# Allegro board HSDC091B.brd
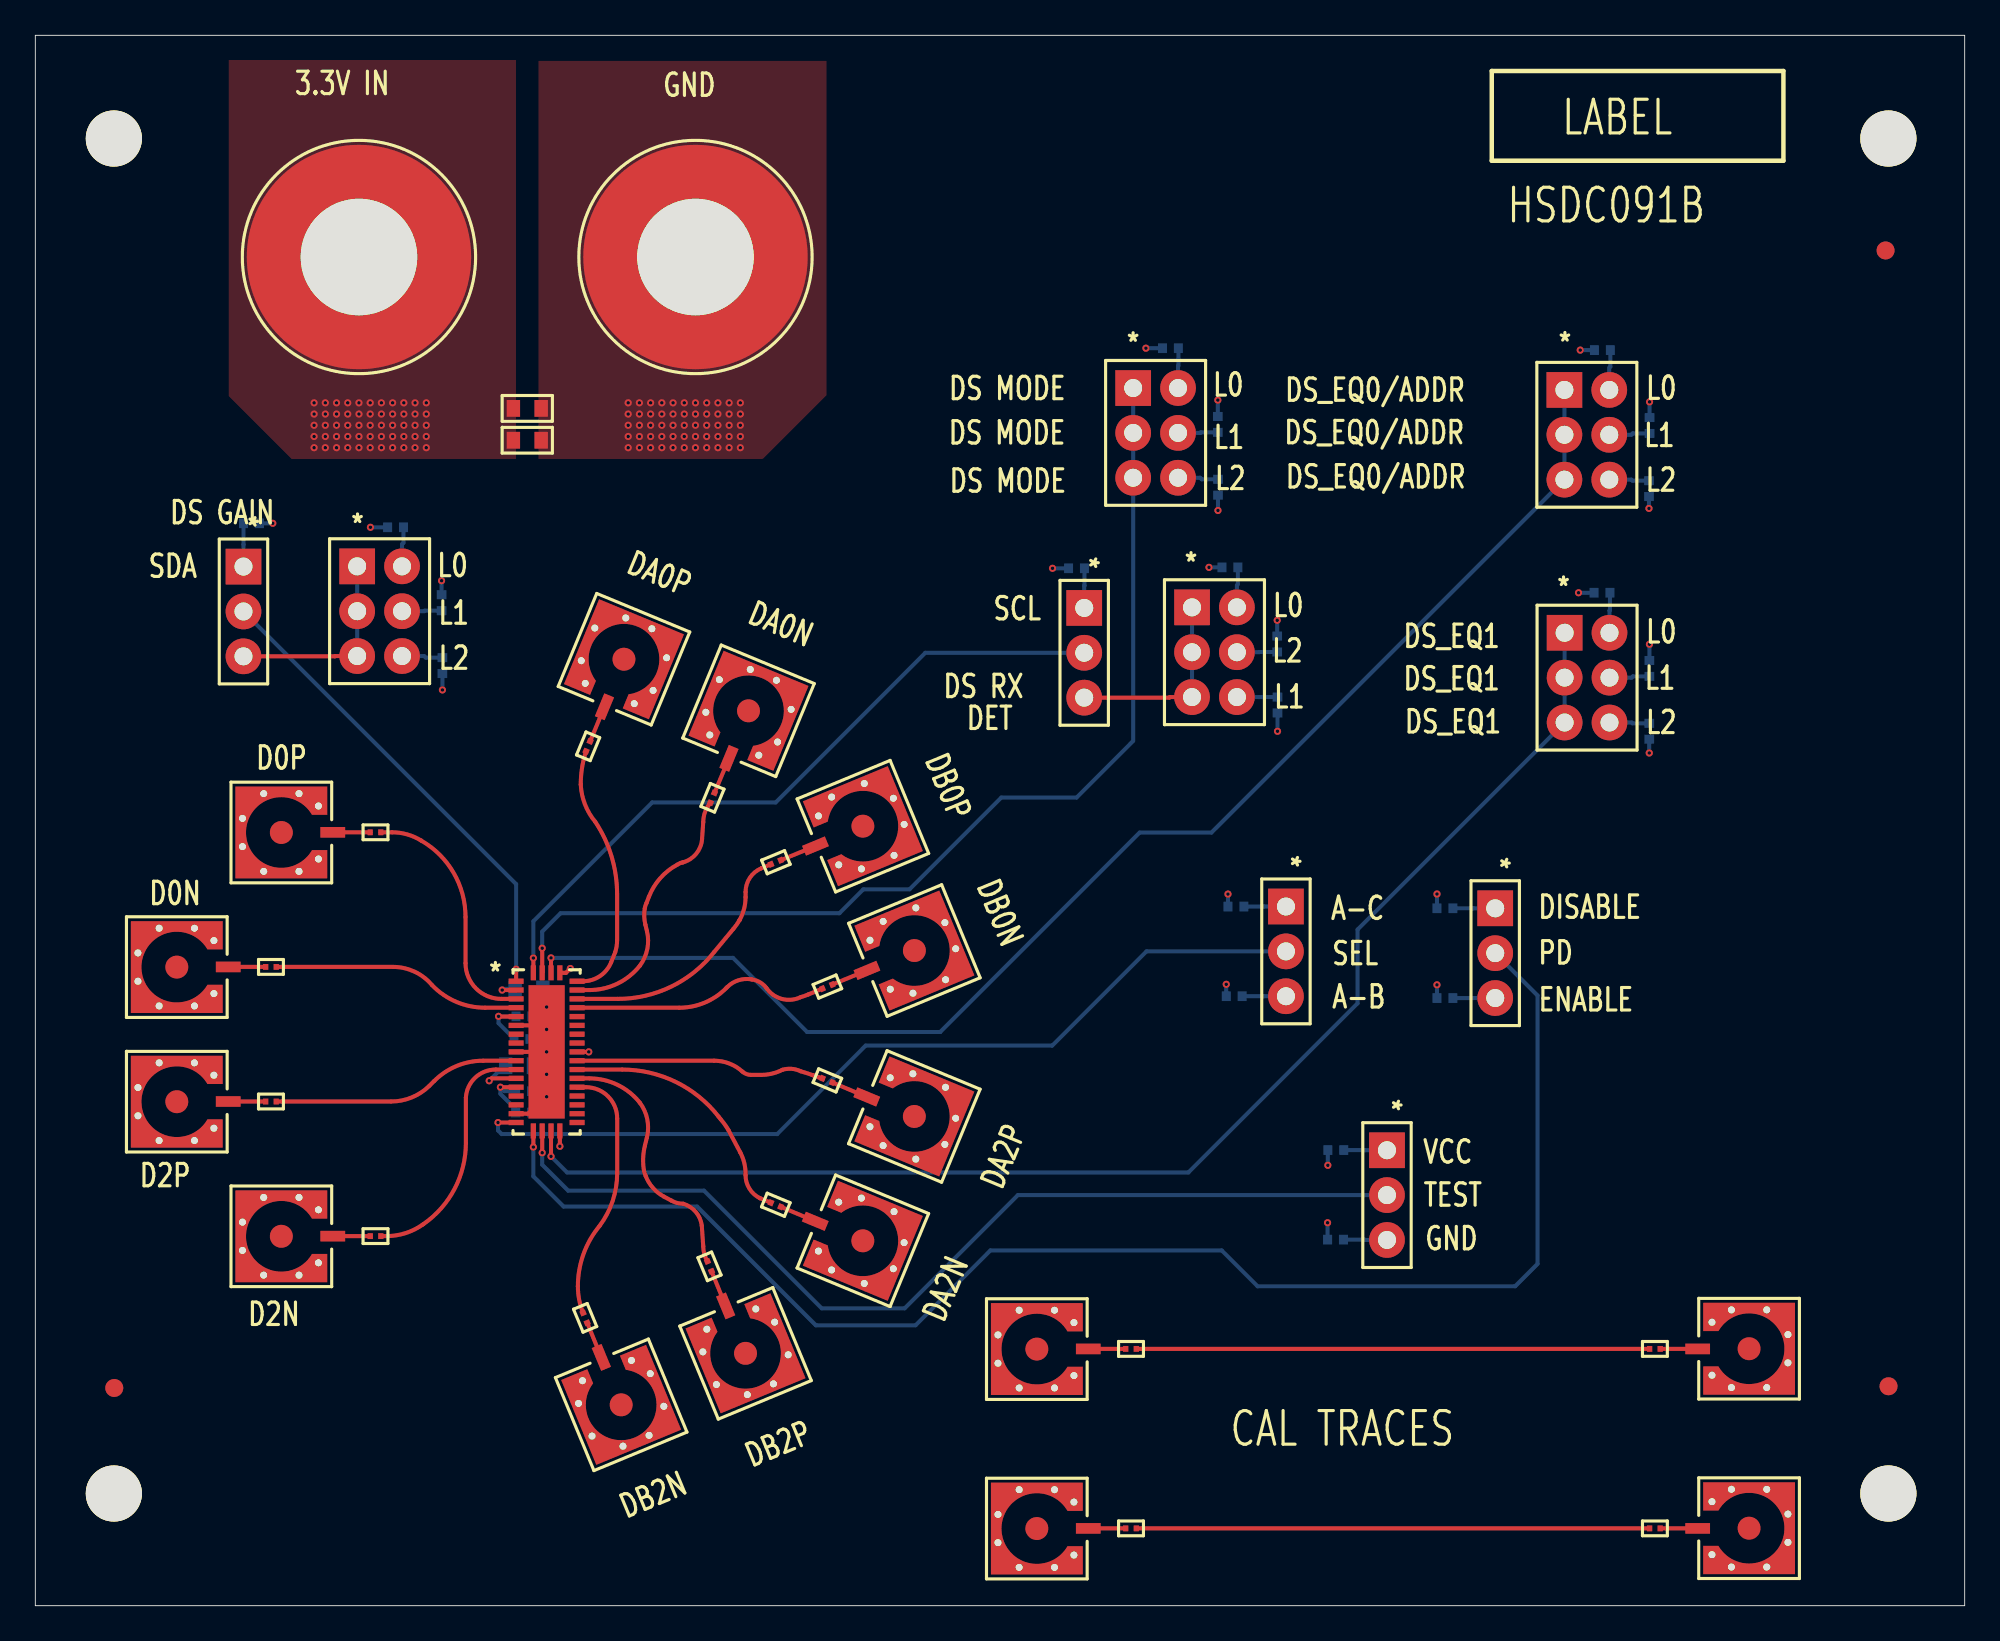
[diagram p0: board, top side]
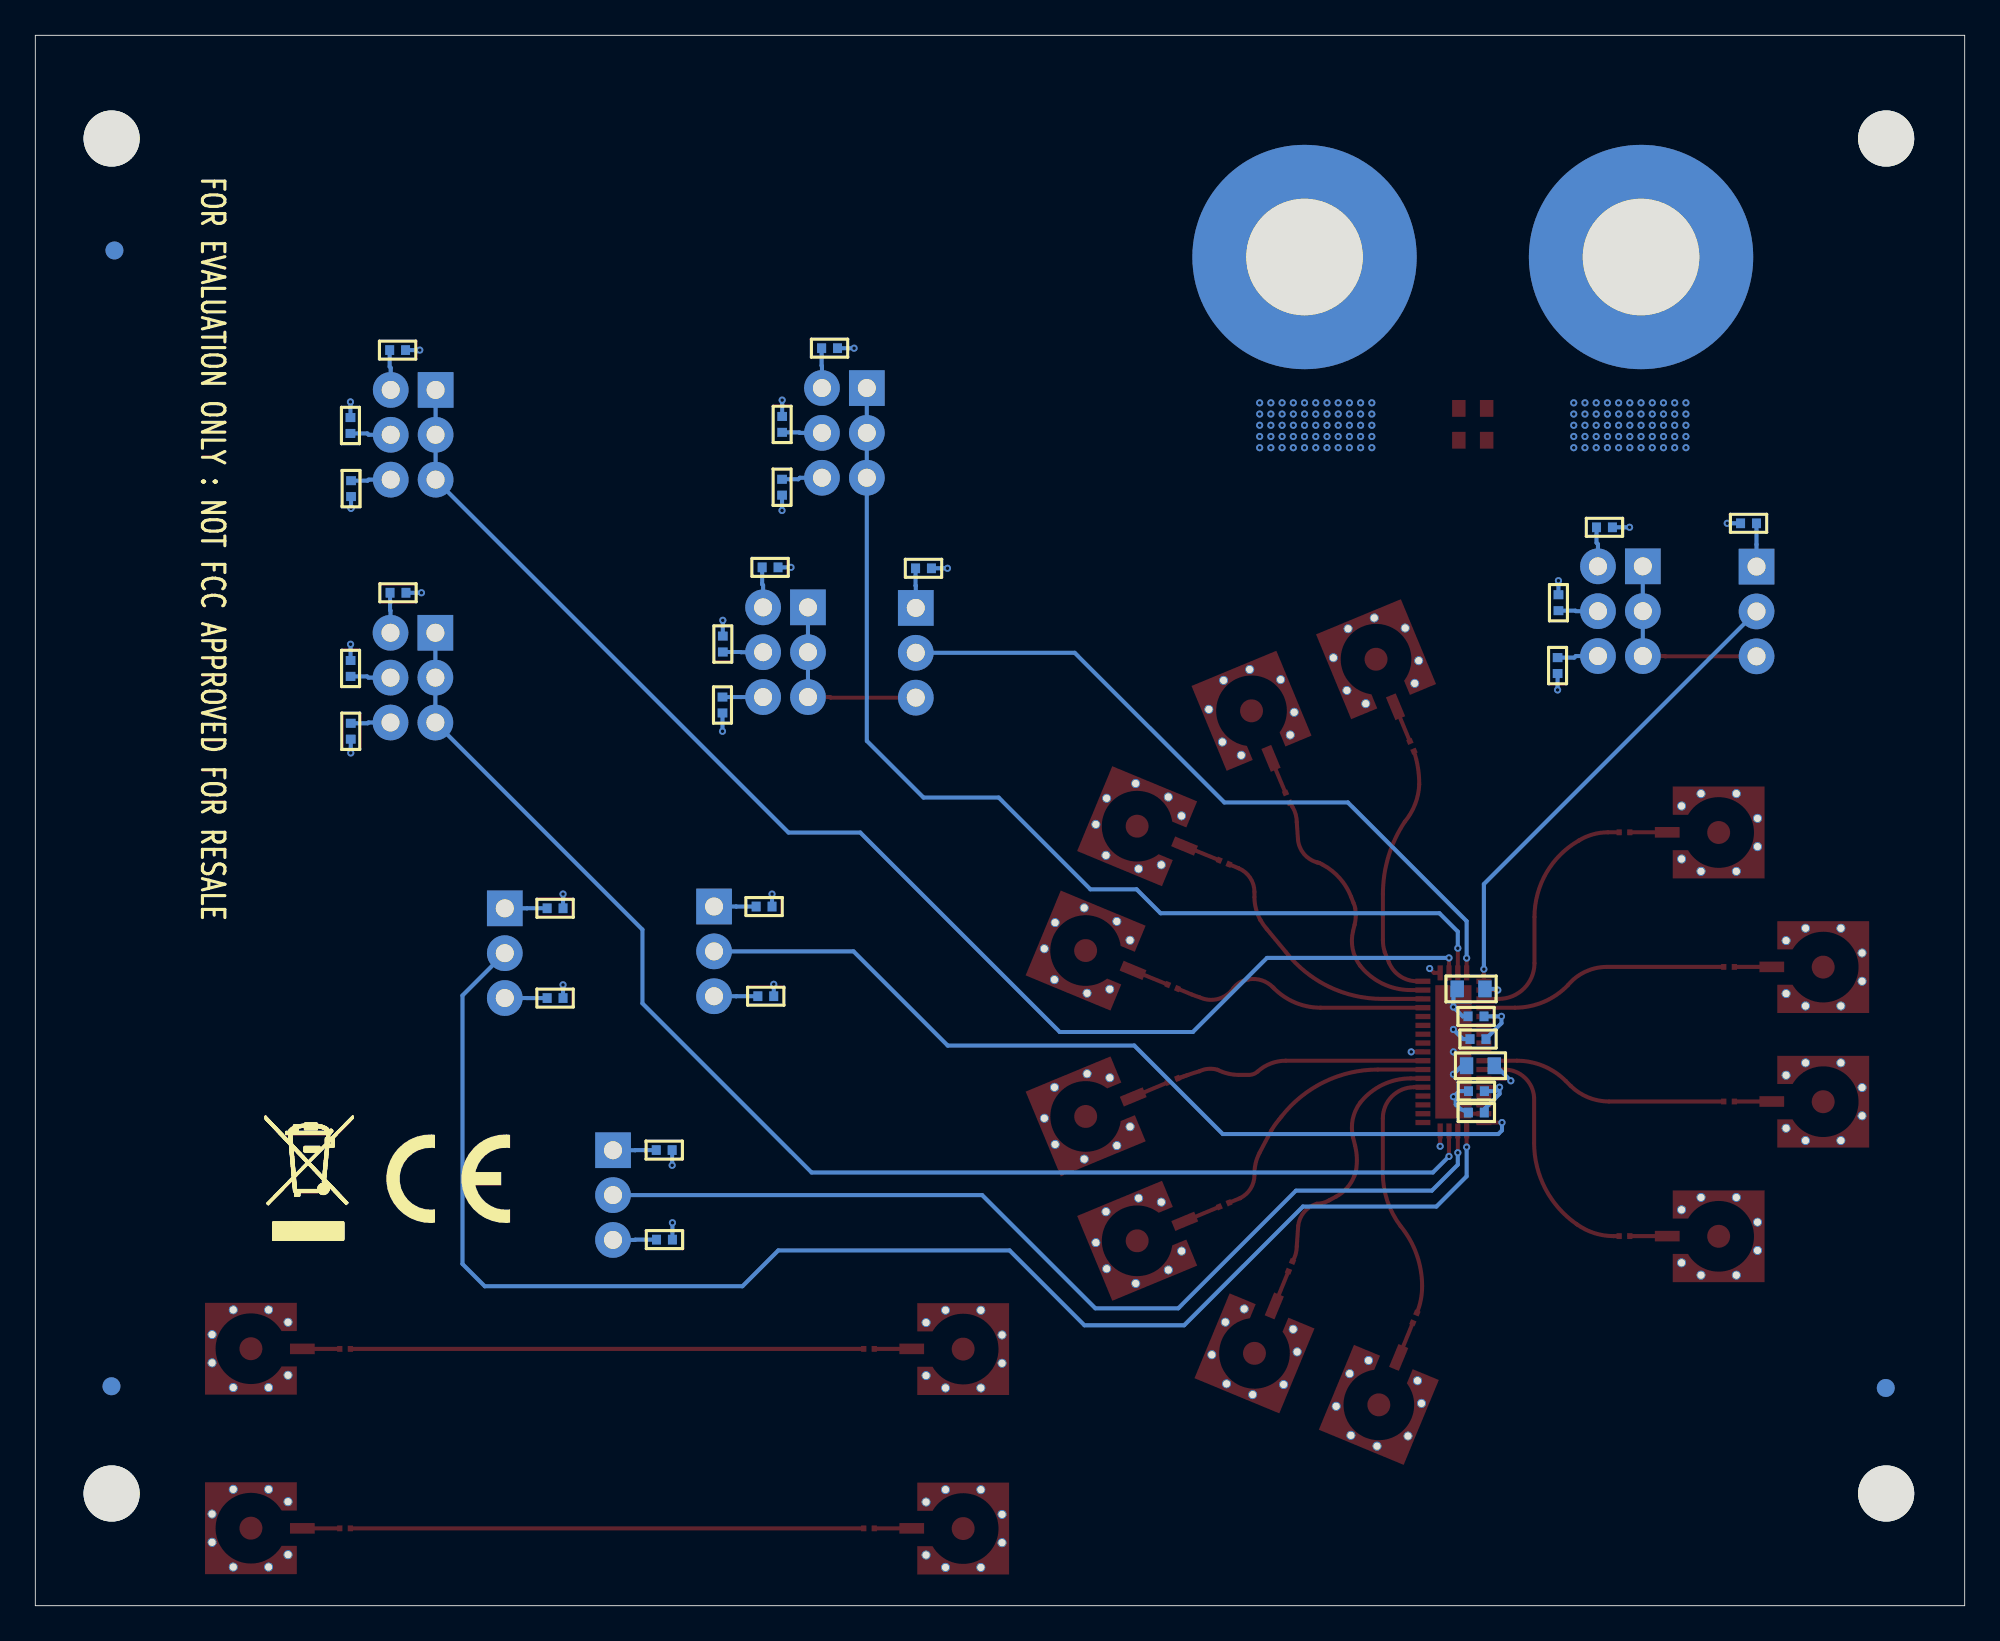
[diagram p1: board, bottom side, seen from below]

Outline 109.22 x 88.9 mm; copper layers: TOP, L2, L3, BOTTOM. Coordinates in mm from the lower left corner of the outline.
Outline path: 0,88.9 109.22,88.9 109.22,0 0,0 0,88.9

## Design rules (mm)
constraint set DEFAULT: min track width 0.229

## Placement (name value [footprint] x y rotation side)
C1  10uF  [CAP_0603]  27.85 67.78 0 top
C2  1uF  [CAP_0603]  27.85 65.98 0 top
C3  0.1uF  [CAP_0402]  27.66 33.36 0 bottom
C4  0.01uF  [CAP_0402]  27.64 29.13 0 bottom
C5  0.22uF  [CAP_0201]  91.68 4.38 0 top
C6  0.22uF  [CAP_0201]  91.68 14.54 0 top
C7  0.22uF  [CAP_0201]  31.29 48.65 247.5 top
C8  0.22uF  [CAP_0201]  38.33 45.73 247.5 top
C9  0.22uF  [CAP_0201]  41.92 42.09 202.5 top
C10  0.22uF  [CAP_0201]  44.84 35.05 202.5 top
C11  0.22uF  [CAP_0201]  44.84 29.74 157.5 top
C12  0.22uF  [CAP_0201]  41.92 22.7 157.5 top
C13  0.22uF  [CAP_0201]  38.16 19.21 112.5 top
C14  0.22uF  [CAP_0201]  31.12 16.29 112.5 top
C23  0.22uF  [CAP_0603]  27.41 30.57 0 bottom
C24  0.22uF  [CAP_0603]  27.94 34.92 0 bottom
C25  0.1uF  [CAP_0402]  27.55 32.08 0 bottom
C26  0.01uF  [CAP_0402]  27.65 27.92 0 bottom
J1  SMP  [CON_SMVT_19S101-40ML5_R04350]  56.7 4.37 90 top
J2  SMP  [CON_SMVT_19S101-40ML5_R04350]  97.02 4.39 270 top
J3  SMP  [CON_SMVT_19S101-40ML5_R04350]  56.7 14.53 90 top
J4  SMP  [CON_SMVT_19S101-40ML5_R04350]  97.02 14.55 270 top
J5  SMP  [CON_SMVT_19S101-40ML5_R04350]  13.93 43.77 90 top
J6  SMP  [CON_SMVT_19S101-40ML5_R04350]  8.01 36.15 90 top
J7  SMP  [CON_SMVT_19S101-40ML5_R04350]  8.01 28.53 90 top
J8  SMP  [CON_SMVT_19S101-40ML5_R04350]  13.93 20.91 90 top
J13  SMP  [CON_SMVT_19S101-40ML5_R04350]  33.32 53.58 337.5 top
J14  SMP  [CON_SMVT_19S101-40ML5_R04350]  40.37 50.66 337.5 top
J15  SMP  [CON_SMVT_19S101-40ML5_R04350]  46.85 44.13 292.5 top
J16  SMP  [CON_SMVT_19S101-40ML5_R04350]  49.76 37.09 292.5 top
J17  SMP  [CON_SMVT_19S101-40ML5_R04350]  49.76 27.7 247.5 top
J18  SMP  [CON_SMVT_19S101-40ML5_R04350]  46.84 20.66 247.5 top
J19  SMP  [CON_SMVT_19S101-40ML5_R04350]  40.2 14.29 202.5 top
J20  SMP  [CON_SMVT_19S101-40ML5_R04350]  33.16 11.37 202.5 top
JMP1  HDR3X1 M .1  [HDR_THVT_1X3_254_871]  70.8 37.04 270 top
JMP2  HDR3X1 M .1  [HDR_THVT_1X3_254_871]  82.64 36.94 270 top
JMP3  HDR3X1 M .1  [HDR_THVT_1X3_254_871]  11.78 56.28 270 top
JMP4  HDR3X1 M .1  [HDR_THVT_2X3_254_871]  18.22 58.84 0 top
JMP5  HDR3X1 M .1  [HDR_THVT_2X3_254_871]  62.15 68.93 0 top
JMP6  HDR3X1 M .1  [HDR_THVT_1X3_254_871]  59.38 53.94 270 top
JMP7  HDR3X1 M .1  [HDR_THVT_2X3_254_871]  65.48 56.52 0 top
JMP8  HDR3X1 M .1  [HDR_THVT_2X3_254_871]  86.56 68.83 0 top
JMP9  HDR3X1 M .1  [HDR_THVT_2X3_254_871]  86.57 55.08 0 top
JMP10  HDR3X1 M .1  [HDR_THVT_1X3_254_871]  76.52 23.24 270 top
NOREF  -  []  -3.81 -69.85 0 top
NOREF#2  -  [unnamed#2]  104.74 76.72 0 top
NOREF#3  -  []  0 0 0 top
NOREF#4  -  [unnamed#2]  104.9 6.35 0 top
NOREF#5  -  []  0 88.9 0 top
NOREF#6  -  [unnamed#2]  4.45 83.06 0 top
NOREF#7  -  [unnamed#2]  4.45 6.35 0 top
NOREF#8  -  []  46.51 80 0 top
NOREF#9  -  []  109.22 0 90 top
NOREF#10  -  [unnamed#2]  104.9 83.06 0 top
NOREF#11  -  [unnamed#2]  104.91 12.42 0 top
NOREF#12  -  []  88.9 38.1 0 top
NOREF#13  -  [unnamed#2]  4.47 12.32 0 top
NOREF#14  -  []  21.54 7.7 180 bottom
NOREF#15  -  []  93.71 24.74 180 bottom
NOREF#16  -  [unnamed#2]  104.74 76.72 180 bottom
NOREF#17  -  [unnamed#2]  4.47 12.32 180 bottom
NOREF#18  -  [unnamed#2]  104.91 12.42 180 bottom
NOREF#19  -  []  85.84 24.17 180 bottom
P1  Banana-Jack  [BJ_THVT_3267]  18.32 76.35 0 top
P2  Banana-Jack  [BJ_THVT_3267]  37.37 76.35 0 top
R1  0  [RES_0201]  19.26 43.78 0 top
R2  0  [RES_0201]  13.34 36.16 0 top
R3  0  [RES_0201]  13.34 28.54 0 top
R4  0  [RES_0201]  19.26 20.92 0 top
R9  0  [RES_0201]  62.03 4.38 0 top
R10  0  [RES_0201]  62.03 14.54 0 top
R11  2k  [RES_0402]  67.97 39.58 0 bottom
R12  2k  [RES_0402]  67.87 34.5 180 bottom
R13  2k  [RES_0402]  79.8 39.48 0 bottom
R14  2k  [RES_0402]  79.8 34.4 180 bottom
R15  1k  [RES_0402]  20.39 61.05 180 bottom
R16  13k  [RES_0402]  23 56.78 90 bottom
R17  59k  [RES_0402]  23.05 53.22 270 bottom
R18  4.7K  [RES_0402]  12.24 61.27 180 bottom
R19  4.7K  [RES_0402]  58.94 58.73 0 bottom
R20  1k  [RES_0402]  67.62 58.78 180 bottom
R21  13k  [RES_0402]  70.3 54.44 90 bottom
R22  59k  [RES_0402]  70.32 50.99 270 bottom
R23  1k  [RES_0402]  64.26 71.19 180 bottom
R24  13k  [RES_0402]  66.94 66.87 90 bottom
R25  59k  [RES_0402]  66.95 63.32 270 bottom
R26  1k  [RES_0402]  88.71 71.08 180 bottom
R27  13k  [RES_0402]  91.38 66.81 90 bottom
R28  59k  [RES_0402]  91.35 63.24 270 bottom
R29  1k  [RES_0402]  88.69 57.34 180 bottom
R30  13k  [RES_0402]  91.37 53.06 90 bottom
R31  59k  [RES_0402]  91.36 49.5 270 bottom
R32  2k  [RES_0402]  73.62 25.79 0 bottom
R33  2k  [RES_0402]  73.6 20.72 180 bottom
U1  TMUXHS4412  [RUA0042BA_205X755]  28.94 31.35 0 top

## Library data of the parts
C1 C2 C23 C24 = cc0603
C3 C4 C25 C26 = cc0402
C5-C14 = cc0201
J1-J8 J13-J20 = SMP_0
JMP1-JMP3 JMP6 JMP10 = HDR3X1 M .1
JMP4 JMP5 JMP7-JMP9 = HDR3X1 M _2.1
P1 P2 = Banana-Jack
R1-R4 R9 R10 = r0201
R11-R33 = r0402
U1 = HD3SS3212_10

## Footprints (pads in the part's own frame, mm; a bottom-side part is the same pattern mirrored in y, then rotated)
BJ_THVT_3267
  round 12.7 hole 6.6: 1(0,0)
CAP_0201
  rect 0.3x0.33 smd: 1(-0.3,0) 2(0.3,0)
CAP_0402
  rect 0.51x0.55 smd: 1(-0.45,0) 2(0.45,0)
CAP_0603
  rect 0.76x0.95 smd: 1(-0.787,0) 2(0.787,0)
CON_SMVT_19S101-40ML5_R04350
  rect 0.6x1.4 smd: 1(0.01,-2.911)
  custom 1.3x1.3 smd: 2(0,0)
  round 0.508 hole 0.4: 3(0.8,2.2) 4(-0.8,2.2) 5(-2.2,1) 6(-2.2,-1) 7(-1.5,-2.1) 8(1.5,-2.1) 9(2.2,-1) 10(2.2,1)
HDR_THVT_1X3_254_871
  rect 2.02x2.02 hole 1.02: 1(-2.54,0)
  round 2.02 hole 1.02: 2(0,0) 3(2.54,0)
HDR_THVT_2X3_254_871
  rect 2.02x2.02 hole 1.02: 1(0,0)
  round 2.02 hole 1.02: 2(2.54,0) 3(0,-2.54) 4(2.54,-2.54) 5(0,-5.08) 6(2.54,-5.08)
RES_0201
  rect 0.3x0.33 smd: 1(-0.3,0) 2(0.3,0)
RES_0402
  rect 0.51x0.55 smd: 1(-0.45,0) 2(0.45,0)
RUA0042BA_205X755
  rect 0.85x0.3 smd: 1(-1.725,4) 2(-1.725,3.5) 3(-1.725,3) 4(-1.725,2.5) 5(-1.725,2) 6(-1.725,1.5) 7(-1.725,1) 8(-1.725,0.5) 9(-1.725,0) 10(-1.725,-0.5) 11(-1.725,-1) 12(-1.725,-1.5) 13(-1.725,-2) 14(-1.725,-2.5) 15(-1.725,-3) 16(-1.725,-3.5) 17(-1.725,-4) 22(1.725,-4) 23(1.725,-3.5) 24(1.725,-3) 25(1.725,-2.5) 26(1.725,-2) 27(1.725,-1.5) 28(1.725,-1) 29(1.725,-0.5) 30(1.725,0) 31(1.725,0.5) 32(1.725,1) 33(1.725,1.5) 34(1.725,2) 35(1.725,2.5) 36(1.725,3) 37(1.725,3.5) 38(1.725,4)
  rect 0.3x0.85 smd: 18(-0.75,-4.475) 19(-0.25,-4.475) 20(0.25,-4.475) 21(0.75,-4.475) 39(0.75,4.475) 40(0.25,4.475) 41(-0.25,4.475) 42(-0.75,4.475)
  rect 2.05x7.55 smd: 43(0,0)
unnamed#2
  round 1.016 smd: (0,0)

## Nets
GND: C1.2 C2.2 C3.2 C4.2 C23.2 C24.2 C25.2 C26.2 J1.2 J1.3 J1.4 J1.5 J1.6 J1.7 J1.8 J1.9 J1.10 J2.2 J2.3 J2.4 J2.5 J2.6 J2.7 J2.8 J2.9 J2.10 J3.2 J3.3 J3.4 J3.5 J3.6 J3.7 J3.8 J3.9 J3.10 J4.2 J4.3 J4.4 J4.5 J4.6 J4.7 J4.8 J4.9 J4.10 J5.2 J5.3 J5.4 J5.5 J5.6 J5.7 J5.8 J5.9 J5.10 J6.2 J6.3 J6.4 J6.5 J6.6 J6.7 J6.8 J6.9 J6.10 J7.2 J7.3 J7.4 J7.5 J7.6 J7.7 J7.8 J7.9 J7.10 J8.2 J8.3 J8.4 J8.5 J8.6 J8.7 J8.8 J8.9 J8.10 J13.2 J13.3 J13.4 J13.5 J13.6 J13.7 J13.8 J13.9 J13.10 J14.2 J14.3 J14.4 J14.5 J14.6 J14.7 J14.8 J14.9 J14.10 J15.2 J15.3 J15.4 J15.5 J15.6 J15.7 J15.8 J15.9 J15.10 J16.2 J16.3 J16.4 J16.5 J16.6 J16.7 J16.8 J16.9 J16.10 J17.2 J17.3 J17.4 J17.5 J17.6 J17.7 J17.8 J17.9 J17.10 J18.2 J18.3 J18.4 J18.5 J18.6 J18.7 J18.8 J18.9 J18.10 J19.2 J19.3 J19.4 J19.5 J19.6 J19.7 J19.8 J19.9 J19.10 J20.2 J20.3 J20.4 J20.5 J20.6 J20.7 J20.8 J20.9 J20.10 P2.1(V) R12.2 R14.2 R15.2 R16.2 R17.2 R20.2 R21.2 R22.2 R23.2 R24.2 R25.2 R26.2 R27.2 R28.2 R29.2 R30.2 R31.2 R33.2 U1.6 U1.9 U1.16 U1.21 U1.30 U1.39 U1.43
VCC3P3: C1.1 C2.1 C3.1 C4.1 C25.1 C26.1 P1.1(V) R11.1 R13.1 R18.1 R19.1 R32.1 U1.5 U1.13(VCC1)
D0N: R2.2 U1.4
D0P: R1.2 U1.3
D2N: R4.2 U1.11
D2P: R3.2 U1.10
DA0N: C8.2 U1.37
DA0P: C7.2 U1.38
DA2N: C12.2 U1.28
DA2P: C11.2 U1.29
DB0N: C10.2 U1.35
DB0P: C9.2 U1.36
DB2N: C14.2 U1.26
DB2P: C13.2 U1.27
DS_EQ0/ADDR: JMP8.1 JMP8.3 JMP8.5 U1.40
DS_EQ1: JMP9.1 JMP9.3 JMP9.5 U1.20
DS_GAIN/SDA: JMP3.2 U1.1
DS_MODE: JMP5.1 JMP5.3 JMP5.5 U1.41
DS_RX_DET/SCL: JMP6.2 U1.42
DS_VREG1: C24.1 U1.2
DS_VREG2: C23.1 U1.12
PD: JMP2.2 U1.18
PD_PD: JMP2.3 R14.1
PD_PU: JMP2.1 R13.2
SEL: JMP1.2 U1.17
SEL_PD: JMP1.3 R12.1
SEL_PU: JMP1.1 R11.2
TEST: JMP10.2 U1.19
N04565: J6.1 R2.1
N04868: J7.1 R3.1
N04879: J8.1 R4.1
N102672: J5.1 R1.1
N16790356: J1.1 R9.1
N16790359: C5.1 R9.2
N16790362: C5.2 J2.1
N16790601: C6.1 R10.2
N16790603: C6.2 J4.1
N16798070: J3.1 R10.1
N16819141: C8.1 J14.1
N16819616: C10.1 J16.1
N16819620: C9.1 J15.1
N16819971: C11.1 J17.1
N16819975: C12.1 J18.1
N16820243: C13.1 J19.1
N16820247: C14.1 J20.1
N16832703: JMP3.1 R18.2
N16832833: JMP6.1 R19.2
N16847290: JMP5.6 R25.1
N16847293: JMP5.4 R24.1
N16847298: JMP5.2 R23.1
N16847609: JMP8.2 R26.1
N16847613: JMP8.4 R27.1
N16847617: JMP8.6 R28.1
N16848254: JMP9.2 R29.1
N16848258: JMP9.4 R30.1
N16848262: JMP9.6 R31.1
N16848700: JMP3.3 JMP4.1 JMP4.3 JMP4.5
N16848778: JMP4.2 R15.1
N16848782: JMP4.4 R16.1
N16848786: JMP4.6 R17.1
N16849265: JMP6.3 JMP7.1 JMP7.3 JMP7.5
N16849344: JMP7.2 R20.1
N16849348: JMP7.4 R21.1
N16849352: JMP7.6 R22.1
N16857633: JMP10.1 R32.2
N16857638: JMP10.3 R33.1
N167939020: C7.1 J13.1

Pads without a net: U1 7 8 14 15 22 23 24 25 31 32 33 34

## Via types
v1: diameter 0.406, hole 0.203, TOP to BOTTOM, 153 vias

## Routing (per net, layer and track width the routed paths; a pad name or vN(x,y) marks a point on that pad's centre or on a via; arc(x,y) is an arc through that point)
GND: length 213.2
  TOP w0.229: v1(28.94,32.62) 28.5,32.62 28.27,32.85 U1.6 ; U1.21 v1(29.69,26.01) ; U1.16 27.88,27.85 v1(28.94,28.81) ; v1(30.29,36.07) 30.04,35.83 U1.39 ; U1.9 v1(28.94,31.35) ; U1.30 v1(31.33,31.35)
  L2 w0.229: J2.8 94.92,3.32 ; J2.8 94.48,2.89 ; J2.8 95.35,2.89 ; J2.8 94.92,2.45 ; J8.9 14.93,23.54 ; J8.9 15.36,23.11 ; J8.9 14.49,23.11 ; 47.25,37.24 J16.7 ; J16.7 47.68,37.67 ; J16.7 47.25,38.1 ; J16.7 46.82,37.67 ; J14.5 39.15,52.43 ; J14.5 38.72,51.99 ; J14.5 38.29,52.43 ; J14.5 38.72,52.86 ; 57.26,6.57 J1.9 ; J1.9 58.13,6.57 ; J1.9 57.7,7 ; J6.8 10.11,38.08 ; J6.8 10.54,37.65 ; J6.8 10.11,37.22 ; J6.8 9.68,37.65 ; J3.6 58.13,12.33 ; J3.6 57.26,12.33 ; J3.6 57.7,11.89 ; 54.5,3.13 J1.4 ; J1.4 54.06,3.57 ; J1.4 54.5,4 ; J18.10 47.36,18.24 ; J18.10 46.93,17.81 ; J18.10 46.49,18.24 ; 35.74,53.23 J13.10 ; J13.10 35.74,54.09 ; J13.10 36.17,53.66 ; 34.75,9.21 J20.4 35.18,9.64 ; J1.7 58.8,3.3 ; J1.7 59.23,2.87 ; J1.7 58.8,2.43 ; J1.7 58.36,2.87 ; J15.7 44.77,44.71 ; J15.7 43.9,44.71 ; J15.7 44.33,44.28 ; J15.7 44.33,45.14 ; 55.26,6.57 J1.10 ; J1.10 55.7,7 ; J1.10 56.13,6.57 ; J5.9 14.93,46.4 ; J5.9 14.49,45.97 ; J5.9 15.36,45.97 ; J3.10 55.7,17.16 ; J3.10 55.26,16.73 ; J3.10 56.13,16.73 ; 58.36,16.03 J3.8 ; J3.8 58.8,15.59 ; J3.8 58.8,16.46 ; J3.8 59.23,16.03 ; J16.8 48.4,35.33 ; J16.8 48.83,34.9 ; J16.8 48.4,34.47 ; J16.8 47.96,34.9 ; 16.03,21.98 J8.8 ; J8.8 16.03,22.84 ; J8.8 15.59,22.41 ; J8.8 16.46,22.41 ; 47.25,26.68 J17.8 ; J17.8 47.68,27.11 ; J17.8 46.81,27.11 ; J17.8 47.25,27.55 ; J8.3 11.73,22.14 ; J8.3 11.29,21.71 ; J8.3 11.73,21.28 ; J5.4 11.73,43.4 ; J5.4 11.29,42.97 ; J5.4 11.73,42.54 ; J6.10 7.01,38.78 ; J6.10 7.44,38.35 ; J6.10 6.58,38.35 ; 45.05,41.94 J15.8 ; J15.8 45.48,41.51 ; J15.8 45.48,42.37 ; J15.8 45.91,41.94 ; 11.29,44.57 J5.3 ; J5.3 11.73,44.14 ; J5.3 11.73,45 ; 97.58,16.75 J4.5 ; J4.5 98.02,17.18 ; J4.5 98.45,16.75 ; J19.3 40.74,11.95 ; J19.3 39.87,11.95 ; J19.3 40.31,11.51 ; 45.05,22.85 J18.7 ; J18.7 45.48,22.41 ; J18.7 45.91,22.85 ; J18.7 45.48,23.28 ; J18.4 49.18,20.99 ; J18.4 49.62,20.55 ; J18.4 49.18,20.12 ; J3.3 54.5,15.76 ; J3.3 54.06,15.33 ; J3.3 54.5,14.89 ; 37.79,13.93 J19.9 ; J19.9 37.36,14.37 ; J19.9 37.79,14.8 ; 14.49,41.57 J5.6 ; J5.6 15.36,41.57 ; J5.6 14.93,41.14 ; 7.01,25.9 J7.5 ; J7.5 6.58,26.33 ; J7.5 7.44,26.33 ; J16.5 49.85,39.94 ; J16.5 50.28,39.5 ; J16.5 49.41,39.5 ; J15.6 45.08,46.21 ; J15.6 45.51,45.78 ; J15.6 44.65,45.78 ; J15.6 45.08,45.35 ; 40.95,47.71 J14.8 ; J14.8 41.39,48.15 ; J14.8 40.95,48.58 ; J14.8 40.52,48.15 ; J20.10 31.95,9.6 ; J20.10 31.51,10.04 ; J20.10 31.51,9.17 ; J20.10 31.08,9.6 ; J13.5 31.67,55.78 ; J13.5 31.24,55.35 ; J13.5 32.11,55.35 ; J13.5 31.67,54.91 ; 12.49,18.71 J8.5 ; J8.5 12.93,18.28 ; J8.5 13.36,18.71 ; 38.18,48.86 J14.7 ; J14.7 37.75,49.29 ; J14.7 38.61,49.29 ; J14.7 38.18,49.73 ; J14.9 42.02,49.33 ; J14.9 42.45,48.89 ; J14.9 41.59,48.89 ; J14.9 42.02,48.46 ; 9.68,30.03 J7.8 ; J7.8 10.11,29.6 ; J7.8 10.11,30.46 ; J7.8 10.54,30.03 ; J6.3 5.81,37.38 ; J6.3 5.38,36.95 ; J6.3 5.81,36.52 ; J19.8 38.02,16.08 ; J19.8 37.58,15.65 ; J19.8 38.45,15.65 ; J19.8 38.02,15.22 ; J3.7 59.23,13.03 ; J3.7 58.8,12.59 ; J3.7 58.8,13.46 ; J3.7 58.36,13.03 ; J4.3 99.65,13.75 ; J4.3 99.22,13.31 ; J4.3 99.22,14.18 ; J18.9 45.08,19.44 ; J18.9 45.51,19.01 ; J18.9 45.08,18.57 ; J18.9 44.65,19.01 ; J15.10 49.05,42.48 ; J15.10 48.61,42.05 ; J15.10 48.61,42.91 ; J15.10 48.18,42.48 ; 12.49,45.97 J5.10 ; J5.10 12.93,46.4 ; J5.10 13.36,45.97 ; 5.38,29.33 J7.3 ; J7.3 5.81,29.76 ; J7.3 5.81,28.9 ; 32.99,55.92 J13.4 ; J13.4 33.86,55.92 ; J13.4 33.43,56.35 ; 51.92,38.67 J16.4 51.49,39.1 ; J6.9 9.44,38.35 ; J6.9 8.58,38.35 ; J6.9 9.01,38.78 ; J4.6 96.45,16.75 ; J4.6 95.58,16.75 ; J4.6 96.02,17.18 ; 58.36,5.87 J1.8 ; J1.8 58.8,6.3 ; J1.8 58.8,5.43 ; J1.8 59.23,5.87 ; J15.3 49.19,44.66 ; J15.3 49.19,43.8 ; J15.3 49.62,44.23 ; 8.58,26.33 J7.6 ; J7.6 9.01,25.9 ; J7.6 9.44,26.33 ; 40.35,16.8 J19.7 ; J19.7 40.79,16.37 ; J19.7 40.79,17.23 ; J19.7 41.22,16.8 ; 49.84,24.85 J17.10 ; J17.10 50.27,25.28 ; J17.10 49.41,25.28 ; 51.49,25.68 J17.3 51.92,26.11 ; J14.4 40.47,53.43 ; J14.4 40.91,53 ; J14.4 40.04,53 ; 7.01,33.52 J6.5 ; J6.5 6.58,33.95 ; J6.5 7.44,33.95 ; J18.5 48.61,22.74 ; J18.5 48.18,22.31 ; J18.5 49.04,22.31 ; J18.5 48.61,21.87 ; 35.34,55.31 J13.3 34.9,55.74 ; J20.6 34.81,13.57 ; J20.6 35.25,13.14 ; J20.6 34.38,13.14 ; J20.6 34.81,12.7 ; J13.8 34.34,51.07 ; J13.8 33.47,51.07 ; J13.8 33.9,50.63 ; J13.8 33.9,51.5 ; J18.8 44.76,20.07 ; J18.8 44.33,19.64 ; J18.8 43.9,20.07 ; J18.8 44.33,20.51 ; J2.9 96.45,2.19 ; J2.9 95.58,2.19 ; J2.9 96.02,1.75 ; 42.22,12.56 41.79,12.56 41.79,12.13 ; 12.49,23.11 J8.10 ; J8.10 12.93,23.54 ; J8.10 13.36,23.11 ; 46.33,23.07 J18.6 ; J18.6 46.76,23.5 ; J18.6 47.19,23.07 ; 9.68,27.03 J7.7 ; J7.7 10.54,27.03 ; J7.7 10.11,26.6 ; J7.7 10.11,27.46 ; J2.5 98.02,7.02 ; J2.5 97.58,6.59 ; J2.5 98.45,6.59 ; 49.25,30.11 J17.6 ; J17.6 50.11,30.11 ; J17.6 49.68,30.54 ; J5.7 16.03,42.7 ; J5.7 15.59,42.27 ; J5.7 16.03,41.84 ; J5.7 16.46,42.27 ; J14.10 43.22,50.74 ; J14.10 42.79,50.31 ; J14.10 42.79,51.17 ; 48.39,29.45 J17.7 ; J17.7 47.96,29.89 ; J17.7 48.83,29.89 ; J17.7 48.39,30.32 ; 14.49,18.71 J8.6 ; J8.6 15.36,18.71 ; J8.6 14.93,18.28 ; J20.7 34.18,13.88 ; J20.7 33.75,13.45 ; J20.7 33.31,13.88 ; J20.7 33.75,14.32 ; 5.81,27.3 J7.4 ; J7.4 5.38,27.73 ; J7.4 5.81,28.16 ; 55.26,2.17 J1.5 ; J1.5 55.7,1.73 ; J1.5 56.13,2.17 ; J5.8 16.03,45.7 ; J5.8 16.03,44.84 ; J5.8 16.46,45.27 ; J5.8 15.59,45.27 ; J20.5 36.01,11.29 ; J20.5 35.58,11.72 ; J20.5 35.58,10.85 ; 47.56,26.05 J17.9 ; J17.9 47.99,25.61 ; J17.9 48.43,26.05 ; J17.9 47.99,26.48 ; J15.5 47.36,46.54 ; J15.5 46.93,46.98 ; J15.5 46.5,46.54 ; 11.29,20.11 J8.4 ; J8.4 11.73,20.54 ; J8.4 11.73,19.68 ; J4.7 95.35,16.05 ; J4.7 94.92,15.61 ; J4.7 94.48,16.05 ; J4.7 94.92,16.48 ; J17.5 51.53,29.78 ; J17.5 51.53,28.91 ; J17.5 51.09,29.35 ; J17.5 51.96,29.35 ; 31.13,52.21 31.13,52.65 ; 31.13,52.21 31.13,51.78 ; 31.13,52.21 30.7,52.21 ; 31.13,52.21 31.57,52.21 ; J7.9 9.01,31.16 ; J7.9 9.44,30.73 ; J7.9 8.58,30.73 ; J2.6 96.02,7.02 ; J2.6 95.58,6.59 ; J2.6 96.45,6.59 ; J7.10 7.01,31.16 ; J7.10 7.44,30.73 ; J7.10 6.58,30.73 ; 55.26,12.33 J3.5 ; J3.5 55.7,11.89 ; J3.5 56.13,12.33 ; 46.77,41.28 J15.9 ; J15.9 47.2,41.71 ; J15.9 46.33,41.71 ; 98.02,11.91 J4.10 ; J4.10 98.45,12.35 ; J4.10 97.58,12.35 ; J13.9 34.97,52.25 ; J13.9 35.4,51.81 ; J13.9 34.97,51.38 ; J13.9 34.54,51.81 ; 15.59,19.41 J8.7 ; J8.7 16.46,19.41 ; J8.7 16.03,18.98 ; J8.7 16.03,19.84 ; J4.8 95.35,13.05 ; J4.8 94.92,12.61 ; J4.8 94.92,13.48 ; J4.8 94.48,13.05 ; J16.10 51.96,35.44 ; J16.10 51.53,35.01 ; J16.10 51.53,35.87 ; J16.10 51.1,35.44 ; J19.10 38.99,12.52 ; J19.10 38.12,12.52 ; J19.10 38.55,12.09 ; J19.10 38.55,12.95 ; 33.27,8.6 J20.3 ; J20.3 33.7,9.03 ; J20.3 32.83,9.03 ; 5.81,34.92 J6.4 ; J6.4 5.38,35.35 ; J6.4 5.81,35.78 ; 10.11,34.22 J6.7 ; J6.7 9.68,34.65 ; J6.7 10.54,34.65 ; J6.7 10.11,35.08 ; J2.7 95.35,5.89 ; J2.7 94.48,5.89 ; J2.7 94.92,6.32 ; J2.7 94.92,5.45 ; J16.6 48.43,38.74 ; J16.6 48,38.31 ; J16.6 48,39.17 ; J16.6 47.57,38.74 ; J20.8 31.41,12.74 ; J20.8 30.97,12.3 ; J20.8 30.54,12.74 ; J20.8 30.97,13.17 ; 98.02,1.75 J2.10 ; J2.10 98.45,2.19 ; J2.10 97.58,2.19 ; 30.48,53.5 J13.6 ; J13.6 30.91,53.93 ; J13.6 30.91,53.07 ; 9.01,33.52 J6.6 ; J6.6 9.44,33.95 ; J6.6 8.58,33.95 ; J1.6 58.13,2.17 ; J1.6 57.26,2.17 ; J1.6 57.7,1.73 ; 48.57,18.64 J18.3 49,19.07 ; 99.22,4.75 J2.4 ; J2.4 99.65,5.19 ; J2.4 99.22,5.62 ; 95.58,12.35 J4.9 ; J4.9 96.02,11.91 ; J4.9 96.45,12.35 ; J5.5 13.36,41.57 ; J5.5 12.93,41.14 ; J5.5 12.49,41.57 ; J20.9 30.75,11.88 ; J20.9 30.32,11.45 ; J20.9 30.75,11.02 ; 57.26,16.73 J3.9 ; J3.9 58.13,16.73 ; J3.9 57.7,17.16 ; J3.4 54.5,14.16 ; J3.4 54.06,13.73 ; J3.4 54.5,13.29 ; 37.96,50.15 J14.6 ; J14.6 37.52,50.58 ; J14.6 37.96,51.01 ; 52.1,27.59 52.53,27.59 ; 52.1,27.59 52.1,28.03 ; 52.1,27.59 52.1,27.16 ; 99.22,3.15 J2.3 ; J2.3 99.65,3.59 ; J2.3 99.22,4.02 ; J1.3 54.5,5.6 ; J1.3 54.5,4.73 ; J1.3 54.06,5.17 ; 49.25,34.67 J16.9 ; J16.9 50.11,34.67 ; J16.9 49.68,34.24 ; J4.4 99.22,15.78 ; J4.4 99.22,14.91 ; J4.4 99.65,15.35 ; 52.1,36.76 J16.3 ; J16.3 52.1,37.62 ; J16.3 52.53,37.19 ; 48.57,46.14 J15.4 49.01,45.71 ; J19.5 43.05,14.2 ; J19.5 42.62,14.64 ; J19.5 42.62,13.77 ; 41.85,16.05 42.29,16.05 ; 41.85,16.05 41.42,16.05 ; 41.85,16.05 41.85,16.48 ; 41.85,16.05 41.85,15.62 ; 41.95,52.82 J14.3 42.39,52.39
  BOTTOM w0.229: v1(28.94,32.62) 28.4,32.08 C25.2 ; R26.2 v1(87.46,71.08) ; R14.2 v1(79.35,35.15) ; R24.2 v1(66.94,68.25) ; R12.2 v1(67.42,35.18) ; R28.2 v1(91.35,62.12) ; C4.2 28.63,29.13 v1(28.94,28.81) 28.81,28.68 28.81,28.37 28.57,28.13 C26.2 ; R15.2 v1(18.97,61.05) ; R22.2 v1(70.32,49.5) ; C23.2 28.46,30.57 v1(28.94,30.08) ; R33.2 v1(73.15,21.68) ; R23.2 v1(62.87,71.19) ; R30.2 v1(91.37,54.43) ; C24.2 28.73,34.74 28.94,34.54 v1(28.94,33.89) 28.41,33.36 C3.2 ; R27.2 v1(91.38,68.15) ; R17.2 v1(23.05,51.84) ; R29.2 v1(87.36,57.34) ; R21.2 v1(70.3,55.78) ; R20.2 v1(66.44,58.78) ; R25.2 v1(66.95,62) ; R31.2 v1(91.36,48.27) ; R16.2 v1(23,58.03)
  vias: v1(33.56,68.09) v1(33.56,67.46) v1(33.56,66.82) v1(33.56,66.19) v1(33.56,65.55) v1(34.2,68.09) v1(34.2,67.46) v1(34.2,66.82) v1(34.2,66.19) v1(34.2,65.55) v1(34.83,68.09) v1(34.83,67.46) v1(34.83,66.82) v1(34.83,66.19) v1(34.83,65.55) v1(35.47,68.09) v1(35.47,67.46) v1(35.47,66.82) v1(35.47,66.19) v1(35.47,65.55) v1(36.1,68.09) v1(36.1,67.46) v1(36.1,66.82) v1(36.1,66.19) v1(36.1,65.55) v1(36.74,68.09) v1(36.74,67.46) v1(36.74,66.82) v1(36.74,66.19) v1(36.74,65.55) v1(37.37,68.09) v1(37.37,67.46) v1(37.37,66.82) v1(37.37,66.19) v1(37.37,65.55) v1(38.01,68.09) v1(38.01,67.46) v1(38.01,66.82) v1(38.01,66.19) v1(38.01,65.55) v1(38.64,68.09) v1(38.64,67.46) v1(38.64,66.82) v1(38.64,66.19) v1(38.64,65.55) v1(39.28,68.09) v1(39.28,67.46) v1(39.28,66.82) v1(39.28,66.19) v1(39.28,65.55) v1(39.91,68.09) v1(39.91,67.46) v1(39.91,66.82) v1(39.91,66.19) v1(39.91,65.55)
VCC3P3: length 11.3
  TOP w0.229: U1.5 26.23,33.35 v1(26.22,33.36) ; U1.13 v1(26.33,29.35)
  BOTTOM w0.229: C4.1 26.55,29.13 v1(26.33,29.35) 26.33,28.97 27.15,28.15 C26.1 ; R18.1 v1(13.44,61.27) ; C3.1 v1(26.22,33.36) 26.22,32.97 27.1,32.1 C25.1 ; R19.1 v1(57.58,58.73) ; R11.1 v1(67.52,40.28) ; R32.1 v1(73.17,24.93) ; R13.1 v1(79.35,40.29)
  vias: v1(15.78,68.09) v1(15.78,67.46) v1(15.78,66.82) v1(15.78,66.19) v1(15.78,65.55) v1(16.42,68.09) v1(16.42,67.46) v1(16.42,66.82) v1(16.42,66.19) v1(16.42,65.55) v1(17.05,68.09) v1(17.05,67.46) v1(17.05,66.82) v1(17.05,66.19) v1(17.05,65.55) v1(17.69,68.09) v1(17.69,67.46) v1(17.69,66.82) v1(17.69,66.19) v1(17.69,65.55) v1(18.32,68.09) v1(18.32,67.46) v1(18.32,66.82) v1(18.32,66.19) v1(18.32,65.55) v1(18.96,68.09) v1(18.96,67.46) v1(18.96,66.82) v1(18.96,66.19) v1(18.96,65.55) v1(19.59,68.09) v1(19.59,67.46) v1(19.59,66.82) v1(19.59,66.19) v1(19.59,65.55) v1(20.23,68.09) v1(20.23,67.46) v1(20.23,66.82) v1(20.23,66.19) v1(20.23,65.55) v1(20.86,68.09) v1(20.86,67.46) v1(20.86,66.82) v1(20.86,66.19) v1(20.86,65.55) v1(21.5,68.09) v1(21.5,67.46) v1(21.5,66.82) v1(21.5,66.19) v1(21.5,65.55) v1(22.13,68.09) v1(22.13,67.46) v1(22.13,66.82) v1(22.13,66.19) v1(22.13,65.55)
D0N: length 14.2
  TOP w0.229: U1.4 25.46,33.85 arc(23.83,34.18) 22.46,35.13 arc(21.47,35.89) 20.26,36.16 R2.2
D0P: length 14.2
  TOP w0.229: R1.2 20.2,43.78 arc(21.05,43.66) 21.84,43.31 21.84,43.31 arc(23.68,41.49) 24.35,38.98 24.35,36.37 arc(24.95,34.94) 26.37,34.35 U1.3
D2N: length 14.2
  TOP w0.229: U1.11 26.06,30.35 arc(24.9,29.89) 24.37,28.77 24.37,26.19 arc(23.74,23.61) 21.98,21.61 21.92,21.57 arc(20.95,21.09) 19.87,20.92 R4.2
D2P: length 14.2
  TOP w0.229: R3.2 20.13,28.54 arc(21.31,28.77) 22.31,29.43 22.59,29.71 arc(23.85,30.55) 25.35,30.85 U1.10
DA0N: length 14.8
  TOP w0.229: U1.37 31.37,34.85 arc(32.95,35.21) 34.22,36.23 arc(34.64,37.16) 34.62,38.19 34.54,38.55 arc(34.47,39.01) 34.5,39.48 arc(34.54,39.63) 34.6,39.78 34.73,40.13 arc(35.38,41.19) 36.35,41.95 36.52,42.04 arc(36.57,42.06) 36.62,42.07 36.68,42.09 arc(37.42,42.57) 37.74,43.4 37.81,44.36 arc(37.87,44.8) 38.05,45.21 arc(38.13,45.34) C8.2
DA0P: length 14.9
  TOP w0.229: U1.38 31.01,35.35 arc(31.97,35.64) 32.59,36.42 32.83,36.99 arc(32.91,37.33) 32.93,37.68 32.93,40.29 arc(32.62,42.43) 31.7,44.38 arc(31.11,45.37) 30.88,46.49 arc(30.95,47.44) C7.2
DA2N: length 14.8
  TOP w0.229: C12.2 41.02,23.07 arc(40.42,23.61) 40.2,24.38 arc(40.14,25.03) 39.91,25.65 39.24,26.91 arc(39.04,27.23) 38.8,27.53 38.68,27.69 arc(36.26,29.65) 33.22,30.35 U1.28
DA2P: length 14.9
  TOP w0.229: 44.58,29.81 44.58,29.81 arc(44.29,29.93) 43.99,30.04 ; U1.29 38.43,30.85 arc(39.29,30.69) 40.03,30.24 arc(40.25,30.1) 40.51,30.05 41.09,30.05 arc(41.71,30.12) 42.29,30.34 arc(42.81,30.39) 43.32,30.26 arc(43.66,30.15) 43.99,30.04 ; C11.2 43.99,30.04
DB0N: length 14.8
  TOP w0.229: C10.2 43.75,34.6 arc(43.54,34.52) 43.32,34.45 arc(42.26,34.35) 41.39,34.96 arc(41.04,35.28) 40.59,35.45 40.53,35.46 arc(39.8,35.4) 39.17,35.02 39.09,34.94 arc(37.88,34.13) 36.46,33.85 U1.35
DB0P: length 14.8
  TOP w0.229: C9.2 41.11,41.75 arc(40.45,41.21) 40.21,40.4 40.21,40.11 arc(40.12,39.44) 39.87,38.81 arc(39.7,38.55) 39.51,38.31 38.44,37.01 arc(36.01,35.05) 32.97,34.35 U1.36
DB2N: length 14.8
  TOP w0.229: U1.26 31.17,29.35 arc(32.42,28.83) 32.94,27.58 32.94,24.49 arc(32.68,22.91) 31.94,21.49 arc(31.03,19.89) 30.71,18.08 arc(30.79,17.31) C14.2
DB2P: length 14.8
  TOP w0.229: U1.27 31.37,29.85 arc(32.95,29.49) 34.22,28.48 arc(34.64,27.54) 34.62,26.51 34.51,26.04 arc(34.41,25.34) 34.46,24.63 arc(34.49,24.47) 34.55,24.32 arc(34.97,23.65) 35.59,23.15 35.99,22.94 arc(36.32,22.8) 36.67,22.75 arc(37.39,22.29) 37.73,21.51 37.81,20.34 arc(37.87,19.9) C13.2
DS_EQ0/ADDR: length 78
  TOP w0.229: U1.40 v1(29.19,36.67)
  BOTTOM w0.229: JMP8.1 JMP8.3 JMP8.5 66.58,43.77 62.52,43.77 51.23,32.48 43.69,32.48 39.5,36.67 v1(29.19,36.67)
DS_EQ1: length 77.3
  TOP w0.229: U1.20 v1(29.19,25.43)
  BOTTOM w0.229: v1(29.19,25.43) 30.1,24.52 65.28,24.52 74.85,34.1 74.85,38.28 JMP9.5 JMP9.3 JMP9.1
DS_GAIN/SDA: length 27.3
  TOP w0.229: U1.1 v1(27.22,36.03)
  BOTTOM w0.229: v1(27.22,36.03) 27.22,40.85 JMP3.2
DS_MODE: length 60.2
  TOP w0.229: U1.41 v1(28.69,37.22)
  BOTTOM w0.229: v1(28.69,37.22) 28.69,38.16 29.73,39.2 45.52,39.2 46.87,40.55 49.49,40.55 54.69,45.75 58.94,45.75 62.15,48.96 JMP5.5 JMP5.3 JMP5.1
DS_RX_DET/SCL: length 40.4
  TOP w0.229: U1.42 v1(28.19,36.66)
  BOTTOM w0.229: JMP6.2 50.38,53.94 41.91,45.47 34.92,45.47 28.19,38.75 v1(28.19,36.66)
DS_VREG1: length 1.5
  TOP w0.229: U1.2 v1(26.43,34.85)
  BOTTOM w0.229: v1(26.43,34.85) 26.49,34.92 C24.1
DS_VREG2: length 2.9
  TOP w0.229: v1(25.69,29.72) 25.83,29.85 U1.12
  BOTTOM w0.229: v1(25.69,29.72) 26.54,30.57 C23.1
PD: length 84.6
  TOP w0.229: U1.18 v1(28.19,25.96)
  BOTTOM w0.229: v1(28.19,25.96) 28.19,24.31 29.9,22.6 37.46,22.6 44.19,15.87 49.83,15.87 54.07,20.11 67.16,20.11 69.19,18.08 83.77,18.08 85.04,19.35 85.04,34.54 JMP2.2
PD_PD: length 2.4
  BOTTOM w0.229: JMP2.3 81.39,34.4 81.39,34.4 R14.1
PD_PU: length 2.4
  BOTTOM w0.229: R13.2 81.39,39.48 81.39,39.48 JMP2.1
SEL: length 50.4
  TOP w0.229: U1.17 v1(26.19,27.35)
  BOTTOM w0.229: v1(26.19,27.35) 26.19,26.91 26.4,26.7 42,26.7 47.01,31.71 57.57,31.71 62.9,37.04 JMP1.2
SEL_PD: length 2.5
  BOTTOM w0.229: JMP1.3 69.55,34.5 69.54,34.5 R12.1
SEL_PU: length 2.4
  BOTTOM w0.229: JMP1.1 69.55,39.58 69.54,39.58 R11.2
TEST: length 55.8
  TOP w0.229: U1.19 v1(28.69,25.64)
  BOTTOM w0.229: v1(28.69,25.64) 28.69,24.97 30.17,23.5 37.86,23.5 44.52,16.83 49.21,16.83 55.62,23.24 JMP10.2
N04565: length 2.1
  TOP w0.229: R2.1 J6.1
N04868: length 2.1
  TOP w0.229: R3.1 J7.1
N04879: length 2.1
  TOP w0.229: R4.1 J8.1
N102672: length 2.1
  TOP w0.229: R1.1 J5.1
N16790356: length 2.1
  TOP w0.229: J1.1 R9.1
N16790359: length 29.1
  TOP w0.229: R9.2 C5.1
N16790362: length 2.1
  TOP w0.229: C5.2 J2.1
N16790601: length 29.1
  TOP w0.229: R10.2 C6.1
N16790603: length 2.1
  TOP w0.229: C6.2 J4.1
N16798070: length 2.1
  TOP w0.229: J3.1 R10.1
N16819141: length 2.1
  TOP w0.229: C8.1 J14.1
N16819616: length 2.1
  TOP w0.229: C10.1 47.08,35.96
N16819620: length 2.1
  TOP w0.229: C9.1 J15.1
N16819971: length 2.1
  TOP w0.229: C11.1 J17.1
N16819975: length 2.1
  TOP w0.229: C12.1 J18.1
N16820243: length 2.1
  TOP w0.229: C13.1 J19.1
N16820247: length 2.1
  TOP w0.229: C14.1 J20.1
N16832703: length 2.5
  BOTTOM w0.229: JMP3.1 11.78,60.08 11.79,60.08 R18.2
N16832833: length 2.2
  BOTTOM w0.229: R19.2 59.39,57.75 59.38,57.74 JMP6.1
N16847290: length 2.3
  BOTTOM w0.229: R25.1 66.03,63.77 65.94,63.85 JMP5.6
N16847293: length 2.3
  BOTTOM w0.229: JMP5.4 65.94,66.39 65.97,66.42 R24.1
N16847298: length 2.3
  BOTTOM w0.229: R23.1 64.71,70.21 64.69,70.18 JMP5.2
N16847609: length 2.3
  BOTTOM w0.229: JMP8.2 89.1,70.08 89.16,70.14 R26.1
N16847613: length 2.3
  BOTTOM w0.229: R27.1 90.43,66.36 90.35,66.29 JMP8.4
N16847617: length 2.3
  BOTTOM w0.229: JMP8.6 90.35,63.75 90.41,63.69 R28.1
N16848254: length 2.3
  BOTTOM w0.229: JMP9.2 89.11,56.33 89.14,56.35 R29.1
N16848258: length 2.3
  BOTTOM w0.229: R30.1 90.44,52.61 90.37,52.54 JMP9.4
N16848262: length 2.3
  BOTTOM w0.229: R31.1 90.41,49.95 90.37,50 JMP9.6
N16848700: length 11.5
  TOP w0.229: JMP4.5 16.97,53.76 16.95,53.74 JMP3.3
  BOTTOM w0.229: JMP4.5 JMP4.3 JMP4.1
N16848778: length 2.2
  BOTTOM w0.229: JMP4.2 20.76,60.09 20.84,60.17 R15.1
N16848782: length 2.3
  BOTTOM w0.229: R16.1 22.04,56.33 22.01,56.3 JMP4.4
N16848786: length 2.3
  BOTTOM w0.229: R17.1 22.1,53.67 22.01,53.76 JMP4.6
N16849265: length 11.2
  TOP w0.229: JMP7.5 64.23,51.44 64.2,51.4 JMP6.3
  BOTTOM w0.229: JMP7.5 JMP7.3 JMP7.1
N16849344: length 2.3
  BOTTOM w0.229: R20.1 68.08,57.82 68.02,57.77 JMP7.2
N16849348: length 2.3
  BOTTOM w0.229: JMP7.4 69.27,53.98 69.29,53.99 R21.1
N16849352: length 2.3
  BOTTOM w0.229: R22.1 69.27,51.44 69.27,51.44 JMP7.6
N16857633: length 2.5
  BOTTOM w0.229: JMP10.1 75.27,25.78 75.26,25.79 R32.2
N16857638: length 2.5
  BOTTOM w0.229: JMP10.3 75.27,20.7 75.25,20.72 R33.1
N167939020: length 2.1
  TOP w0.229: C7.1 J13.1

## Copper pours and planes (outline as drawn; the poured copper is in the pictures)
GND on TOP: 28.48,64.92 28.48,87.45 44.8,87.45 44.8,68.53 41.18,64.92
GND on L2: 95.29,0.64 108.61,0.64 108.61,88.25 0.64,88.25 0.64,0.64 95.29,0.64 95.32,-69.85 130.41,-69.85 130.41,-66.04 95.32,-66.04
VCC3P3 on TOP: 14.51,64.92 10.95,68.48 10.95,87.5 27.21,87.5 27.21,64.92
VCC3P3 on L3: 95.29,0.64 108.61,0.64 108.61,88.25 0.64,88.25 0.64,0.64 95.29,0.64 95.32,-69.85 130.41,-69.85 130.41,-66.04 95.32,-66.04

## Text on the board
BOTTOM: LAYER 4 - BOTTOM SIDE
Ref Des/Assembly Bottom: ASSEMBLY- BOTTOM SIDE
Board Geometry/Soldermask Bottom: SOLDERMASK BOTTOM
Package Geometry/Pastemask Bottom: PASTEMASK BOTTOM
Ref Des/Silkscreen Bottom: FOR EVALUATION ONLY : NOT FCC APPROVED FOR RESALE | SILKSCREEN BOTTOM
TOP: LAYER 1 - TOP SIDE
Ref Des/Assembly Top: ASSEMBLY-TOP SIDE
Board Geometry/Soldermask Top: SOLDERMASK TOP
Package Geometry/Pastemask Top: PASTEMASK TOP
Ref Des/Silkscreen Top: D2P | SDA | D0N | DS GAIN | D2N | D0P | 3.3V IN | L0 | L1 | L2 | GND | DS RX | DS MODE | DET | SCL | DS_EQ0/ADDR | A-C | SEL | A-B | DS_EQ1 | VCC | TEST | DISABLE | PD | ENABLE | DB2N | DB2P | DA2N | DA2P | DB0P | DB0N | DA0P | DA0N | SILKSCREEN TOP | CAL TRACES | HSDC091B | LABEL
L2: LAYER 2 - GND PLANE
L3: LAYER 3 - PWR PLANE
XSECTION_CHART: *  SURFACE - AIR 0 MIL | *  DIELECTRIC - SOLDERMASK-0.8MIL 0.8 MIL | L1 TOP CONDUCTOR - COPPER_1/2OZ_PLATED 1.4 MIL | *  DIELECTRIC - FILL_MEGTRON6_4.7 4.7 MIL | L2 L2 PLANE - COPPER_1.0OZ 1.38 MIL | *  DIELECTRIC - CORE_1.10 45 MIL | L3 L3 PLANE - COPPER_1.0OZ 1.38 MIL | L4 BOTTOM CONDUCTOR - COPPER_1/2OZ_PLATED 1.4 MIL | DESIGN CROSS SECTION CHART | ___________________________ | TOTAL THICKNESS 61.56 MIL | 1-4
PAGE_OUTLINE: HSDC091
DIMENSION: FABRICATION DRAWING | CAD ORIGIN
User.6: LAYER 1 | LAYER 2 | LAYER 3 | LAYER 4 | LAYER | NO. | TABLE 1: | TOP | L2_GND | L3_PWR | BOTTOM | NAME | DIFFIRENTIAL PAIR | IMPEDANCE (OHMS) | DIFF TRACE | WIDTH | SPACING | SINGLE ENDED | 50 +/- 10% | TRACE WIDTH | 0.009" | REFERENCE | SPECIAL FAB NOTES: | PLACE DRILL CHART HERE: | 1:FAB SHOP MUST FOLLOW THE SOLDER MASK REVIEW LAYERS. | 2:IMPEDANCES TO MATCH TABLE 1 | 3:Use FR-4 High Tg for the CORE material. | MIN. ANNULAR RING 2 MIL EXTERNAL PER IPC-6012C | REGISTRATION TOLERANCES: METAL +/- X MIL,HOLES +/- X MIL | IMPEDANCE CONTROL: | BOARD SIZE (REFER ALSO ARRAY/PANEL PROFILING INFORMATION) | MIXED DIELECTRIC: | LAMINATE MATERIAL: | THICKNESS: | TOLERANCE: | COPPER THICKNESS (FINISHED): | BOARD FINISH: | NUMBER OF LAYERS: | MIN. TRACK WIDTH: | MIN. CLEARANCE  : | MIN. VIA PAD/DRILL: | THIEVING ALLOWED: | X | OUTER: | INNER SIGNAL: | INNER PLANE: | OTHER: | SILKSCREEN: | SOLDERMASK: (PER IPC-6011,6012) | BOARD SURFACE TREATMENT: | ADDITIONAL REQUIREMENTS: | VENDOR MARKING: | SILKSCREEN COLOR: | SOLDERMASK COLOR: | THROUGH-HOLE VIA TREATMENT: | VIA FILL USING NON-CONDUCTIVE EPOXY: | FOR WIRE BONDING: | VENDOR DATE CODE,UL,LOGO: | IPC-6012C CLASS 3 | FR-4 HIGH Tg | 0.062" +/-10% | IPC-6012C CLASS 2 | MICRO-SECTION | CERTIFICATES OF COMPLIANCE | NICKEL/GOLD (ENIG) | IMMERSION TIN | HARD GOLD | IN AN OPEN AREA | 1/4 OZ. | OPEN | NO | 4 | 9.0 MIL | 7.87 MIL | 16/08 MIL | NONE | DESIGN INFORMATION | ROGERS 4350B | 0.093" +/-10% | YES | TDR REPORTS/COUPONS | WHITE | GREEN | SOFT GOLD | TENTED | 1/2 OZ. | BOW & TWIST: | ORGANIC (OSP) | OTHER | WHERE INDICATED (SEE DRAWING) | YES - SEE TABLE 1 | ETCH | IDENTIFIER: | BLUE | RoHS | 1.0 OZ. | SILKSCREEN | PER SUPPLIED ARTWORK | ALL 10 MIL VIAS | ALL x MIL VIAS | ELECTRICAL TEST | UL 94V-0 | MEGTRON 6 | HASL | 2.0 OZ. | BREAK-AWAY | ENEPIG
User.10: FIGURE | FINISHED_SIZE | 8.0 | 15.75 | 40.16 | 259.84 | 125.0 | TOLERANCE_DRILL | +3.0/-8.0 | +3.15/-3.15 | +2.0/-2.0 | DRILL CHART: TOP to BOTTOM | ALL UNITS ARE IN MILS | TOLERANCE_TRAVEL | - | PLATED | NON-PLATED | QTY | 153 | 128 | 45 | 2 | 4 | 332 | TOTAL HOLES:
